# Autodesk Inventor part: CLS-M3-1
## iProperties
Author: RON CRAIN
Shininess: 85.0
Length Units: 11269
Angle Units: 11284
Time Units: 11279
Mass Units: 11290
Length Display Precision: 2
Angle Display Precision: 1
Compacted: True
PropertySet Name: _Private Model Information
Created: 2001-02
Part Number: CLS-M3-1
Material: Stainless Steel, Austenitic
Description: NUT, SELF CLINCH, STAINLESS STEEL, M3x0.5
Vendor: PENN MFG. & ENG
Document SubType Name: Modeling
Designer: RON CRAIN
Control State: 0
Master: False
Checked Out: False
PropertySet Name: Design Tracking Control
Density: 0.0
Volumn: 0.0
Area: 0.0
PropertySet Name: Model Information
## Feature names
1. Revolution1
